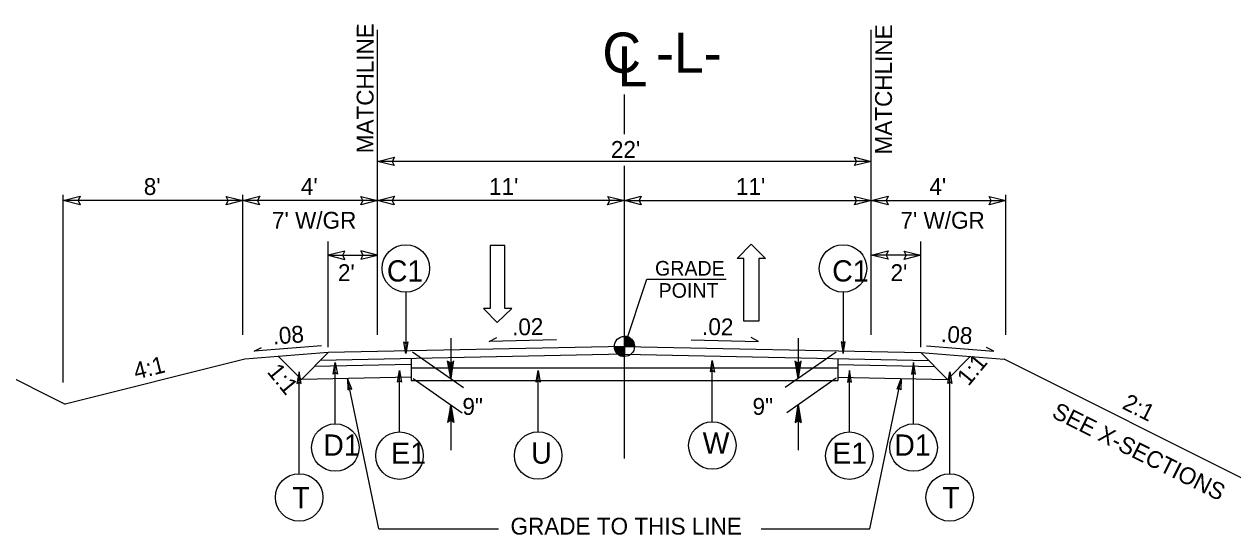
# Model space of a CAD drawing. Extents: x 575722 to 576066, y -53107 to -52774.
# Drawn here: x 575878.8 to 575932.7, y -53056.8 to -53034 of the extents above; entities that cross this region are included whole.
import ezdxf

# ---------------------------------------------------------------- set-up
doc = ezdxf.new("R2010")
doc.units = 0
for name, color, linetype in [('Prop Dimension Text', 7, 'Continuous'), ('Prop DSN Text', 7, 'Continuous'), ('Prop Lane Arrow CELL', 7, 'Continuous'), ('Prop Terminator CELL', 7, 'Continuous'), ('Typical Grade Point Symbol CELL', 7, 'Continuous'), ('Typical ID Circle CELL', 7, 'Continuous'), ('Typical Pavement Slope CELL', 7, 'Continuous'), ('Typical Slope Point Local CELL', 7, 'Continuous'), ('Typical Terminator CELL', 7, 'Continuous'), ('Typical Text Centerline CELL', 7, 'Continuous'), ('Typical Text Grade Point CELL', 7, 'Continuous'), ('Typical Text ID Circle CELL', 7, 'Continuous')]:
    doc.layers.add(name, color=color, linetype=linetype)

# ---------------------------------------------------------------- blocks, each defined once
blk = doc.blocks.new('TERMINATOR')
at = {"layer": 'Typical Terminator CELL'}
blk.add_lwpolyline([(-0.469, 0.081), (0, 0), (-0.471, -0.083), (-0.411, 0)], close=True, dxfattribs=at)

msp = doc.modelspace()

# ---------------------------------------------------------------- linework, layer by layer
at = {"layer": 'Prop Dimension Text'}
for p, q in [((575894.575, -53047.837), (575894.575, -53034.254)), ((575916.575, -53047.837), (575916.575, -53034.254)), ((575916.575, -53040.11), (575894.575, -53040.11)), ((575880.575, -53049.968), (575880.575, -53041.607)), ((575888.575, -53041.857), (575880.575, -53041.857)), ((575888.575, -53047.357), (575888.575, -53041.607)), ((575888.575, -53047.837), (575888.575, -53041.607)), ((575894.575, -53041.857), (575888.575, -53041.857)), ((575894.575, -53047.837), (575894.575, -53041.607)), ((575894.575, -53047.357), (575894.575, -53041.607)), ((575894.575, -53047.357), (575894.575, -53041.607)), ((575894.575, -53047.357), (575894.575, -53041.607)), ((575905.575, -53041.857), (575894.575, -53041.857)), ((575905.575, -53041.857), (575916.575, -53041.857)), ((575916.575, -53047.837), (575916.575, -53041.607)), ((575916.575, -53047.357), (575916.575, -53041.607)), ((575916.575, -53047.357), (575916.575, -53041.607)), ((575916.575, -53047.357), (575916.575, -53041.607)), ((575916.575, -53041.857), (575922.575, -53041.857)), ((575922.575, -53047.837), (575922.575, -53041.607)), ((575922.575, -53047.357), (575922.575, -53041.607)), ((575892.369, -53048.395), (575892.369, -53043.683)), ((575918.782, -53048.395), (575918.782, -53043.683)), ((575892.369, -53044.289), (575894.575, -53044.289)), ((575918.782, -53044.289), (575916.575, -53044.289)), ((575891.182, -53049.823), (575890.167, -53048.808)), ((575891.182, -53049.823), (575892.374, -53048.631)), ((575894.563, -53048.588), (575894.568, -53048.593)), ((575916.587, -53048.588), (575916.583, -53048.593)), ((575919.969, -53049.823), (575918.777, -53048.631)), ((575919.969, -53049.823), (575920.984, -53048.808))]:
    msp.add_line(p, q, dxfattribs=at)
at = {"layer": 'Prop DSN Text'}
for p, q in [((575897.837, -53047.995), (575897.837, -53049.79)), ((575913.313, -53047.995), (575913.313, -53049.79)), ((575896.128, -53048.593), (575898.41, -53050.192)), ((575915.004, -53048.606), (575912.741, -53050.192)), ((575897.837, -53049.79), (575897.697, -53049.004)), ((575897.717, -53049.018), (575897.837, -53049.79)), ((575897.837, -53049.79), (575897.739, -53049.033)), ((575897.759, -53049.047), (575897.837, -53049.79)), ((575897.837, -53049.79), (575897.778, -53049.062)), ((575897.798, -53049.076), (575897.837, -53049.79)), ((575897.837, -53049.79), (575897.818, -53049.091)), ((575897.837, -53049.79), (575897.976, -53049.004)), ((575897.837, -53049.79), (575897.956, -53049.018)), ((575897.937, -53049.033), (575897.837, -53049.79)), ((575897.837, -53049.79), (575897.917, -53049.047)), ((575897.896, -53049.062), (575897.837, -53049.79)), ((575897.837, -53049.79), (575897.877, -53049.076)), ((575897.857, -53049.091), (575897.837, -53049.79)), ((575897.837, -53049.106), (575897.837, -53049.79)), ((575913.313, -53049.79), (575913.175, -53049.004)), ((575913.313, -53049.79), (575913.194, -53049.018)), ((575913.214, -53049.033), (575913.313, -53049.79)), ((575913.313, -53049.79), (575913.234, -53049.047)), ((575913.254, -53049.062), (575913.313, -53049.79)), ((575913.313, -53049.79), (575913.274, -53049.076)), ((575913.294, -53049.091), (575913.313, -53049.79)), ((575913.313, -53049.79), (575913.453, -53049.004)), ((575913.434, -53049.018), (575913.313, -53049.79)), ((575913.313, -53049.79), (575913.412, -53049.033)), ((575913.392, -53049.047), (575913.313, -53049.79)), ((575913.313, -53049.79), (575913.373, -53049.062)), ((575913.353, -53049.076), (575913.313, -53049.79)), ((575913.313, -53049.79), (575913.333, -53049.091)), ((575913.313, -53049.106), (575913.313, -53049.79)), ((575894.639, -53056.483), (575893.242, -53049.78)), ((575896.156, -53049.78), (575898.345, -53051.312)), ((575915.006, -53049.772), (575912.805, -53051.312)), ((575916.512, -53056.483), (575917.908, -53049.78)), ((575897.837, -53050.957), (575897.697, -53051.745)), ((575897.837, -53050.957), (575897.717, -53051.729)), ((575897.739, -53051.715), (575897.837, -53050.957)), ((575897.837, -53050.957), (575897.759, -53051.699)), ((575897.778, -53051.685), (575897.837, -53050.957)), ((575897.837, -53050.957), (575897.798, -53051.672)), ((575897.818, -53051.657), (575897.837, -53050.957)), ((575897.837, -53050.957), (575897.837, -53052.978)), ((575897.837, -53050.957), (575897.976, -53051.745)), ((575897.956, -53051.729), (575897.837, -53050.957)), ((575897.837, -53050.957), (575897.937, -53051.715)), ((575897.917, -53051.699), (575897.837, -53050.957)), ((575897.837, -53050.957), (575897.896, -53051.685)), ((575897.877, -53051.672), (575897.837, -53050.957)), ((575897.837, -53050.957), (575897.857, -53051.657)), ((575897.837, -53051.642), (575897.837, -53050.957)), ((575913.313, -53050.957), (575913.175, -53051.745)), ((575913.194, -53051.729), (575913.313, -53050.957)), ((575913.313, -53050.957), (575913.214, -53051.715)), ((575913.234, -53051.699), (575913.313, -53050.957)), ((575913.313, -53050.957), (575913.254, -53051.685)), ((575913.274, -53051.672), (575913.313, -53050.957)), ((575913.313, -53050.957), (575913.294, -53051.657)), ((575913.313, -53050.957), (575913.313, -53052.978)), ((575913.313, -53050.957), (575913.453, -53051.745)), ((575913.313, -53051.642), (575913.313, -53050.957)), ((575913.333, -53051.657), (575913.313, -53050.957)), ((575913.313, -53050.957), (575913.353, -53051.672)), ((575913.373, -53051.685), (575913.313, -53050.957)), ((575913.313, -53050.957), (575913.392, -53051.699)), ((575913.412, -53051.715), (575913.313, -53050.957)), ((575913.313, -53050.957), (575913.434, -53051.729)), ((575897.837, -53051.642), (575897.697, -53051.745)), ((575897.976, -53051.745), (575897.837, -53051.642)), ((575913.175, -53051.745), (575913.313, -53051.642)), ((575913.313, -53051.642), (575913.453, -53051.745)), ((575894.639, -53056.483), (575899.964, -53056.483)), ((575911.663, -53056.483), (575916.512, -53056.483))]:
    msp.add_line(p, q, dxfattribs=at)
at = {"layer": 'Prop Lane Arrow CELL'}
for p, q in [((575899.591, -53043.863), (575899.591, -53046.663)), ((575900.251, -53043.863), (575899.591, -53043.863)), ((575900.251, -53046.663), (575900.251, -53043.863)), ((575910.601, -53044.432), (575911.221, -53043.802)), ((575911.221, -53043.802), (575911.861, -53044.432)), ((575910.901, -53044.432), (575910.601, -53044.432)), ((575910.901, -53047.232), (575910.901, -53044.432)), ((575911.861, -53044.432), (575911.561, -53044.432)), ((575911.561, -53044.432), (575911.561, -53047.232)), ((575899.591, -53046.663), (575899.291, -53046.663)), ((575899.291, -53046.663), (575899.911, -53047.293)), ((575899.911, -53047.293), (575900.551, -53046.663)), ((575900.551, -53046.663), (575900.251, -53046.663)), ((575911.561, -53047.232), (575910.901, -53047.232))]:
    msp.add_line(p, q, dxfattribs=at)
at = {"layer": 'Prop Terminator CELL'}
for points in [[(575893.43, -53050.256), (575893.242, -53049.78), (575893.258, -53050.295), (575893.333, -53050.213)], [(575917.721, -53050.256), (575917.908, -53049.78), (575917.893, -53050.295), (575917.818, -53050.213)]]:
    msp.add_lwpolyline(points, close=True, dxfattribs=at)
at = {"layer": 'Typical Grade Point Symbol CELL'}
for p, q in [((575905.575, -53048.357), (575906.575, -53045.357)), ((575905.575, -53048.357), (575905.575, -53047.909)), ((575905.128, -53048.357), (575905.575, -53048.357)), ((575905.574, -53048.804), (575905.575, -53048.357)), ((575905.575, -53048.357), (575905.574, -53048.804)), ((575906.023, -53048.357), (575905.575, -53048.357))]:
    msp.add_line(p, q, dxfattribs=at)
for points in [[(575905.579, -53047.909), (575905.579, -53047.909), (575905.579, -53048.357)], [(575905.588, -53047.909), (575905.588, -53048.357)], [(575905.597, -53047.91), (575905.597, -53048.357)], [(575905.606, -53047.91), (575905.606, -53048.357)], [(575905.615, -53047.911), (575905.615, -53048.357)], [(575905.624, -53047.912), (575905.624, -53048.357)], [(575905.633, -53047.913), (575905.633, -53048.357)], [(575905.642, -53047.914), (575905.642, -53048.357)], [(575905.651, -53047.915), (575905.651, -53048.357)], [(575905.66, -53047.917), (575905.66, -53048.357)], [(575905.669, -53047.919), (575905.669, -53048.357)], [(575905.678, -53047.921), (575905.678, -53048.357)], [(575905.687, -53047.923), (575905.687, -53048.357)], [(575905.696, -53047.926), (575905.696, -53048.357)], [(575905.705, -53047.928), (575905.705, -53048.357)], [(575905.714, -53047.931), (575905.714, -53048.357)], [(575905.723, -53047.934), (575905.723, -53048.357)], [(575905.732, -53047.937), (575905.732, -53048.357)], [(575905.741, -53047.941), (575905.741, -53048.357)], [(575905.749, -53047.945), (575905.749, -53048.357)], [(575905.758, -53047.949), (575905.758, -53048.357)], [(575905.767, -53047.953), (575905.767, -53048.357)], [(575905.776, -53047.957), (575905.776, -53048.357)], [(575905.785, -53047.962), (575905.785, -53048.357)], [(575905.794, -53047.967), (575905.794, -53048.357)], [(575905.803, -53047.972), (575905.803, -53048.357)], [(575905.812, -53047.977), (575905.812, -53048.357)], [(575905.821, -53047.983), (575905.821, -53048.357)], [(575905.83, -53047.989), (575905.83, -53048.357)], [(575905.839, -53047.996), (575905.839, -53048.357)], [(575905.848, -53048.002), (575905.848, -53048.357)], [(575905.857, -53048.009), (575905.857, -53048.357)], [(575905.866, -53048.017), (575905.866, -53048.357)], [(575905.875, -53048.025), (575905.875, -53048.357)], [(575905.884, -53048.033), (575905.884, -53048.357)], [(575905.893, -53048.041), (575905.893, -53048.357)], [(575905.902, -53048.05), (575905.902, -53048.357)], [(575905.911, -53048.06), (575905.911, -53048.357)], [(575905.92, -53048.071), (575905.92, -53048.357)], [(575905.929, -53048.082), (575905.929, -53048.357)], [(575905.937, -53048.094), (575905.937, -53048.357)], [(575905.946, -53048.107), (575905.946, -53048.357)], [(575905.955, -53048.121), (575905.955, -53048.357)], [(575905.964, -53048.136), (575905.964, -53048.357)], [(575905.973, -53048.152), (575905.973, -53048.357)], [(575905.982, -53048.171), (575905.982, -53048.357)], [(575905.991, -53048.192), (575905.991, -53048.357)], [(575906, -53048.217), (575906, -53048.357)], [(575906.009, -53048.247), (575906.009, -53048.357)], [(575906.018, -53048.293), (575906.018, -53048.357)], [(575905.13, -53048.357), (575905.13, -53048.406)], [(575905.139, -53048.357), (575905.139, -53048.458)], [(575905.148, -53048.357), (575905.148, -53048.49)], [(575905.157, -53048.357), (575905.157, -53048.517)], [(575905.166, -53048.357), (575905.166, -53048.538)], [(575905.175, -53048.357), (575905.175, -53048.557)], [(575905.184, -53048.357), (575905.184, -53048.574)], [(575905.192, -53048.357), (575905.192, -53048.59)], [(575905.201, -53048.357), (575905.201, -53048.603)], [(575905.21, -53048.357), (575905.21, -53048.616)], [(575905.219, -53048.357), (575905.219, -53048.628)], [(575905.228, -53048.357), (575905.228, -53048.639)], [(575905.237, -53048.357), (575905.237, -53048.65)], [(575905.246, -53048.357), (575905.246, -53048.66)], [(575905.255, -53048.357), (575905.255, -53048.67)], [(575905.264, -53048.357), (575905.264, -53048.679)], [(575905.273, -53048.357), (575905.273, -53048.687)], [(575905.282, -53048.357), (575905.282, -53048.695)], [(575905.291, -53048.357), (575905.291, -53048.703)], [(575905.3, -53048.357), (575905.3, -53048.71)], [(575905.309, -53048.357), (575905.309, -53048.717)], [(575905.318, -53048.357), (575905.318, -53048.723)], [(575905.327, -53048.357), (575905.327, -53048.729)], [(575905.336, -53048.357), (575905.336, -53048.735)], [(575905.345, -53048.357), (575905.345, -53048.741)], [(575905.354, -53048.357), (575905.354, -53048.746)], [(575905.363, -53048.357), (575905.363, -53048.751)], [(575905.372, -53048.357), (575905.372, -53048.756)], [(575905.38, -53048.357), (575905.38, -53048.76)], [(575905.389, -53048.357), (575905.389, -53048.764)], [(575905.398, -53048.357), (575905.398, -53048.768)], [(575905.407, -53048.357), (575905.407, -53048.772)], [(575905.416, -53048.357), (575905.416, -53048.776)], [(575905.425, -53048.357), (575905.425, -53048.779)], [(575905.434, -53048.357), (575905.434, -53048.781)], [(575905.443, -53048.357), (575905.443, -53048.784)], [(575905.452, -53048.357), (575905.452, -53048.786)], [(575905.461, -53048.357), (575905.461, -53048.789)], [(575905.47, -53048.357), (575905.47, -53048.791)], [(575905.479, -53048.357), (575905.479, -53048.793)], [(575905.488, -53048.357), (575905.488, -53048.795)], [(575905.497, -53048.357), (575905.497, -53048.797)], [(575905.506, -53048.357), (575905.506, -53048.798)], [(575905.515, -53048.357), (575905.515, -53048.8)], [(575905.524, -53048.357), (575905.524, -53048.801)], [(575905.533, -53048.357), (575905.533, -53048.802)], [(575905.542, -53048.357), (575905.542, -53048.803)], [(575905.551, -53048.357), (575905.551, -53048.803)], [(575905.56, -53048.357), (575905.56, -53048.804)], [(575905.568, -53048.357), (575905.568, -53048.804), (575905.568, -53048.804)]]:
    msp.add_lwpolyline(points, dxfattribs=at)
msp.add_circle((575905.575, -53048.357), 0.448, dxfattribs=at)
for start, end in [(359.9905, 89.9905), (179.9905, 269.9905)]:
    msp.add_arc((575905.575, -53048.357), 0.448, start, end, dxfattribs=at)
at = {"layer": 'Typical ID Circle CELL'}
for p, q in [((575895.836, -53045.937), (575895.836, -53048.671)), ((575915.314, -53045.937), (575915.314, -53048.671)), ((575892.693, -53051.805), (575892.693, -53049.071)), ((575909.491, -53051.713), (575909.491, -53048.979)), ((575918.458, -53051.805), (575918.458, -53049.071)), ((575891.076, -53054.027), (575891.076, -53049.487)), ((575895.552, -53052.168), (575895.552, -53049.434)), ((575901.733, -53052.161), (575901.733, -53049.427)), ((575915.598, -53052.168), (575915.598, -53049.434)), ((575920.075, -53054.027), (575920.075, -53049.487))]:
    msp.add_line(p, q, dxfattribs=at)
for centre in [(575895.836, -53044.88), (575915.314, -53044.88), (575892.693, -53052.863), (575909.491, -53052.771), (575918.458, -53052.863), (575895.552, -53053.225), (575901.733, -53053.219), (575915.598, -53053.225), (575891.083, -53055.085), (575920.068, -53055.085)]:
    msp.add_circle(centre, 1.058, dxfattribs=at)
at = {"layer": 'Typical Pavement Slope CELL'}
for p, q in [((575892.073, -53048.331), (575889.073, -53048.571)), ((575899.555, -53048.131), (575899.888, -53047.964)), ((575902.555, -53048.068), (575899.555, -53048.131)), ((575908.555, -53048.068), (575911.555, -53048.131)), ((575911.555, -53048.131), (575911.222, -53047.964)), ((575919.037, -53048.331), (575922.037, -53048.571)), ((575892.374, -53048.631), (575888.663, -53048.928)), ((575889.073, -53048.571), (575889.406, -53048.405)), ((575918.777, -53048.631), (575922.488, -53048.928)), ((575922.037, -53048.571), (575921.704, -53048.405)), ((575896.073, -53048.905), (575896.073, -53049.721)), ((575896.073, -53049.308), (575896.073, -53049.875)), ((575915.078, -53048.905), (575915.078, -53049.721)), ((575915.078, -53049.308), (575915.078, -53049.875))]:
    msp.add_line(p, q, dxfattribs=at)
for points in [[(575905.575, -53048.707), (575892.016, -53048.989)], [(575905.575, -53048.357), (575892.374, -53048.631)], [(575905.575, -53048.357), (575918.777, -53048.631)], [(575905.575, -53048.707), (575919.135, -53048.989)], [(575896.073, -53049.155), (575891.761, -53049.244)], [(575896.073, -53049.308), (575915.078, -53049.308)], [(575915.078, -53049.155), (575919.39, -53049.244)], [(575896.073, -53049.721), (575891.182, -53049.823)], [(575896.073, -53049.875), (575915.078, -53049.875)], [(575915.078, -53049.721), (575919.969, -53049.823)]]:
    msp.add_lwpolyline(points, dxfattribs=at)
at = {"layer": 'Typical Slope Point Local CELL'}
for p, q in [((575872.735, -53046.963), (575880.664, -53050.928)), ((575888.663, -53048.928), (575880.664, -53050.928)), ((575933.65, -53054.51), (575922.488, -53048.928))]:
    msp.add_line(p, q, dxfattribs=at)
at = {"layer": 'Typical Terminator CELL'}
for points in [[(575895.925, -53048.156), (575895.836, -53048.671), (575895.745, -53048.153), (575895.836, -53048.219)], [(575915.226, -53048.156), (575915.314, -53048.671), (575915.406, -53048.153), (575915.314, -53048.219)], [(575892.604, -53049.587), (575892.693, -53049.071), (575892.784, -53049.59), (575892.693, -53049.524)], [(575909.402, -53049.495), (575909.491, -53048.979), (575909.583, -53049.497), (575909.491, -53049.432)], [(575918.547, -53049.587), (575918.458, -53049.071), (575918.366, -53049.59), (575918.458, -53049.524)], [(575891.165, -53050.002), (575891.076, -53049.487), (575890.984, -53050.005), (575891.076, -53049.939)], [(575895.464, -53049.949), (575895.552, -53049.434), (575895.644, -53049.952), (575895.552, -53049.886)], [(575901.644, -53049.943), (575901.733, -53049.427), (575901.825, -53049.945), (575901.733, -53049.879)], [(575915.687, -53049.949), (575915.598, -53049.434), (575915.507, -53049.952), (575915.598, -53049.886)], [(575919.986, -53050.002), (575920.075, -53049.487), (575920.166, -53050.005), (575920.075, -53049.939)]]:
    msp.add_lwpolyline(points, close=True, dxfattribs=at)
at = {"layer": 'Typical Text Centerline CELL'}
for p, q in [((575905.575, -53038.902), (575905.575, -53037.124)), ((575905.575, -53053.357), (575905.575, -53040.307))]:
    msp.add_line(p, q, dxfattribs=at)
at = {"layer": 'Typical Text Grade Point CELL'}
msp.add_line((575906.575, -53045.357), (575910.113, -53045.357), dxfattribs=at)

# ---------------------------------------------------------------- block references
at = {"layer": 'Prop Dimension Text', "xscale": 1.5906680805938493, "rotation": 180}
for p, yscale in [((575894.575, -53040.11), 2.2831050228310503), ((575880.575, -53041.857), 2.2831050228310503), ((575888.575, -53041.857), 2.2831050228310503), ((575894.575, -53041.857), 2.2831050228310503), ((575905.575, -53041.857), 2.2831050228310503), ((575916.575, -53041.857), 2.2831050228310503), ((575892.369, -53044.289), -2.2831050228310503), ((575916.575, -53044.289), 2.2831050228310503)]:
    msp.add_blockref('TERMINATOR', p, dxfattribs=dict(at, yscale=yscale))
at = {"layer": 'Prop Dimension Text', "xscale": 1.5906680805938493}
for p, yscale in [((575916.575, -53040.11), 2.2831050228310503), ((575888.575, -53041.857), 2.2831050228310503), ((575894.575, -53041.857), 2.2831050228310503), ((575905.575, -53041.857), 2.2831050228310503), ((575916.575, -53041.857), 2.2831050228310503), ((575922.575, -53041.857), 2.2831050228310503), ((575894.575, -53044.289), -2.2831050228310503), ((575918.782, -53044.289), 2.2831050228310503)]:
    msp.add_blockref('TERMINATOR', p, dxfattribs=dict(at, yscale=yscale))

# ---------------------------------------------------------------- texts
at = {"layer": 'Prop Dimension Text'}
for s, rotation, p in [('MATCHLINE', 89.8989, (575894.392, -53039.748)), ('MATCHLINE', 89.8989, (575917.489, -53039.802)), ('.02', 1.1916, (575900.576, -53047.869)), ('.02', 358.8084, (575909.027, -53047.839)), ('.08', 4.5739, (575889.93, -53048.277)), ('.08', 355.4261, (575919.659, -53048.155))]:
    msp.add_text(s, height=0.75, rotation=rotation, dxfattribs=at).set_placement(p)
for s, p in [("22'", (575904.971, -53039.953)), ("8'", (575884.16, -53041.607)), ("4'", (575891.16, -53041.607)), ("11'", (575899.543, -53041.607)), ("11'", (575910.543, -53041.607)), ("4'", (575919.16, -53041.607)), ("7' W/GR", (575889.872, -53043.109)), ("7' W/GR", (575917.872, -53043.109)), ("2'", (575892.81, -53045.445)), ("2'", (575917.43, -53045.445))]:
    msp.add_text(s, height=0.75, dxfattribs=at).set_placement(p)
at = {"layer": 'Prop DSN Text'}
for s, height, p in [('C -L-', 1.7897, (575904.588, -53036.16)), ('L', 1.79, (575905.265, -53036.767)), ('9" ', 0.75, (575898.356, -53051.406)), ('9" ', 0.75, (575911.283, -53051.406)), ('GRADE TO THIS LINE', 0.75, (575900.499, -53056.741))]:
    msp.add_text(s, height=height, dxfattribs=at).set_placement(p)
at = {"layer": 'Typical Slope Point Local CELL'}
for s, rotation, p in [('4:1', 14.0362, (575883.811, -53049.838)), ('1:1', 50.5662, (575920.905, -53050.16)), ('1:1', 309.4338, (575889.622, -53049.501)), ('SEE X-SECTIONS', 333.434, (575924.568, -53051.491)), ('2:1', 333.434, (575927.705, -53051.102))]:
    msp.add_text(s, height=0.75, rotation=rotation, dxfattribs=at).set_placement(p)
at = {"layer": 'Typical Text Grade Point CELL'}
for s, p in [('GRADE', (575906.939, -53045.201)), ('POINT', (575907.097, -53046.189))]:
    msp.add_text(s, height=0.6525, dxfattribs=at).set_placement(p)
at = {"layer": 'Typical Text ID Circle CELL'}
for s, height, p in [('C1', 0.9469, (575894.991, -53045.464)), ('C1', 0.9469, (575914.833, -53045.464)), ('D1', 0.9469, (575892.158, -53053.226)), ('E1', 0.9469, (575895.181, -53053.588)), ('U', 0.947, (575901.422, -53053.581)), ('W', 0.947, (575909.06, -53053.133)), ('E1', 0.9469, (575914.833, -53053.588)), ('D1', 0.9469, (575917.599, -53053.226)), ('T', 0.947, (575890.777, -53055.564)), ('T', 0.947, (575919.734, -53055.564))]:
    msp.add_text(s, height=height, dxfattribs=at).set_placement(p)

doc.saveas('drawing.dxf')
